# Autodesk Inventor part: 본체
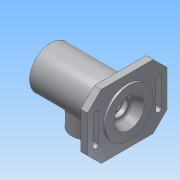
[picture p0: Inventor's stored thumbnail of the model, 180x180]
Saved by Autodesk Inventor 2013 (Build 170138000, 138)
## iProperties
Created: 2017-10
Part Number: 본체
Material: 알루미늄 6061
Document SubType Name: Modeling
Designer: Administrator
Density: 2.71 g/cm^3
Mass: 740.991 g
Surface Area: 653.939 cm^2
Volume: 273.428 cm^3
Author: Administrator
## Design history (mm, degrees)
sketch "스케치1"
  geometry: L1 (-57.5, 0)-(57.5, 0); L2 (-57.5, 0)-(-57.5, 31); L3 (-57.5, 31)-(54.5, 31); L4 (57.5, 0)-(57.5, 22); L5 (57.5, 22)-(43.5, 16); L6 (43.5, 16)-(43.5, 12.5); L7 (43.5, 12.5)-(36.2, 12.5); L8 (36.2, 12.5)-(36.2, 10); L9 (36.2, 10)-(33.5, 10); L10 (33.5, 10)-(33.5, 16.5); L11 (-48.5, 21)-(-48.5, 0); L12 (-48.5, 21)-(-48.5, 24); L13 (-48.5, 24)-(-45.5, 24); L14 (-45.5, 24)-(-45.5, 20); L15 (-45.5, 20)-(-36.5, 20); L16 (-36.5, 20)-(-36.5, 17.5); L17 (-36.5, 17.5)-(-33.25, 17.5); L18 (-33.25, 17.5)-(-33.25, 18.5); L19 (-33.25, 18.5)-(-31.5, 18.5); L20 (-31.5, 18.5)-(-31.5, 17.5); L21 (-31.5, 17.5)-(-20.5, 17.5); L22 (33.5, 16.5)-(28.5, 16.5); L23 (28.5, 16.5)-(28.5, 17.5); L24 (28.5, 17.5)-(17.5, 17.5); L25 (17.5, 17.5)-(17.5, 26); L26 (17.5, 26)-(-20.5, 26); L27 (-20.5, 26)-(-20.5, 17.5); L28 (57.5, 35)-(54.5, 35); L29 (54.5, 35)-(54.5, 31); L30 (57.5, 22)-(57.5, 35); 2 further points
  constraints: 60 end point, 16 perpendicular, 8 parallel, 1 coincident, 1 collinear, 1 horizontal, 1 midpoint, 1 point on line
  dimensions: "d0" = 115 distance of L1.start L1.end; "d1" = 31 distance of L1.start L2.end; "d11" = 14 horizontal distance of L4.end L5.end; "d12" = 6 vertical distance of L4.end L5.end; "d13" = 22 distance of L1.end L4.end; "d14" = 3.5 distance of L5.end L6.end; "d15" = 7.3 distance of L6.end L7.end; "d16" = 2.5 distance of L7.end L8.end; "d17" = 2.7 distance of L8.end L9.end; "d18" = 6.5 distance of L9.end L10.end; "d19" = 9 distance between parallel lines of L2 L11; "d20" = 21 distance of L11.start L11.end; "d21" = 3 distance of L11.start L12.end; "d22" = 3 distance of L12.end L13.end; "d23" = 4 distance of L13.end L14.end; "d25" = 9 distance of L14.end L15.end; "d26" = 2.5 distance of L15.end L16.end; "d27" = 3.25 distance of L16.end L17.end; "d28" = 1 distance of L17.end L18.end; "d29" = 1.75 distance of L18.end L19.end; "d30" = 1 distance of L19.end L20.end; "d31" = 11 distance of L20.end L21.end; "d32" = 5 distance of L10.end L22.end; "d33" = 1 distance of L22.end L23.end; "d34" = 11 distance of L23.end L24.end; "d35" = 8.5 distance of L24.end L25.end; "d102" = 52 diameter of L26 L1; "d114" = 13 distance of L4.end L28.start; "d115" = 4 distance of L3.end L28.end; "d116" = 3 distance of L28.start L28.end; "d117" = 115 horizontal distance of L2.end L28.start
revolve "회전1" sketch "스케치1" stored, may be unused: angle "d36" = 90 deg
hole "구멍1" diameter "d39" = 40.376; stored, may be unused: countersink angle "d43" = 90 deg, drill point angle "d45" = 0 deg; dims "d37" = 10, "d38" = 10, "d40" = 9, "d41" = 4, "d42" = 2, "d44" = 9
fillet "모깎기1" dims "d46" = 3, "d47" = 0.3
chamfer "모따기1" distance "d48" = 1; stored, may be unused: second distance "d49" = 2, angle "d50" = 45 deg
chamfer "모따기2" distance "d51" = 0.7; stored, may be unused: second distance "d52" = 2, angle "d53" = 30 deg
node "작업 평면1"
sketch "스케치2"
  geometry: L1 (-58, 47)-(58, 47); L2 (58, 47)-(58, -47); L3 (58, -47)-(-58, -47); L4 (-58, -47)-(-58, 47); C1 r 31 at (0, 0) reference; C2 r 21.188 at (0, 0) reference; 3 further points
  constraints: 8 end point, 2 midpoint, 2 parallel, 1 horizontal, 1 horizontal alignment, 1 perpendicular, 1 vertical alignment
  dimensions: "d55" = 116 distance of L2.end L3.end; "d56" = 94 distance of L1.end L2.end
extrude "돌출1" join sketch "스케치2" distance "d57" = 10; taper "d58" = 0 deg
chamfer "모따기3" distance "d59" = 20; stored, may be unused: second distance "d60" = 2, angle "d61" = 30 deg
node "작업 평면2"
sketch "스케치4"
  geometry: L1 (57.5, 31)-(57.5, -31) reference; C1 r 25 at (1.5, 0); 1 further point
  constraints: 1 centre point, 1 horizontal alignment
  dimensions: "d72" = 50 diameter of C1; "d74" = 56 distance from line of C1.centre L1
extrude "돌출3" join sketch "스케치4" stored distance "d75" = 10; taper "d76" = 0 deg
hole "구멍2" diameter "d79" = 32; stored, may be unused: countersink angle "d83" = 90 deg, drill point angle "d85" = 0 deg; dims "d77" = 10, "d78" = 10, "d80" = 9, "d81" = 4, "d82" = 2, "d84" = 40
sketch "스케치5"
  geometry: C1 r 16 at (0, 0) reference; 2 further points
  constraints: 1 vertical alignment
  dimensions: "d86" = 20.5 distance of C1.centre point (0, 20.5)
hole "구멍3" sketch "스케치5" at (0, 20.5) diameter "d87" = 2.459; stored, may be unused: countersink angle "d91" = 90 deg, drill point angle "d93" = 120 deg; dims "d88" = 6, "d89" = 4, "d90" = 2, "d92" = 8
fillet "모깎기2" dims "d94" = 3
node "작업 평면3"
sketch "스케치6"
  geometry: L1 (56, 78)-(56, 16) reference; L2 (25, 0)-(-25, 0) reference; 2 further points
  constraints: 1 other
  dimensions: "d95" = 56 distance from line of L1 point (0, 10); "d96" = 10 distance from line of L2 point (0, 10)
feature "엠보싱1" sketch "스케치6" dims "d97" = 0.5, "d98" = 0
sketch "스케치7"
  geometry: L1 (-47, -38)-(-47, 38) reference; L2 (-20, -50)-(20, -50); L3 (-20, -42)-(20, -42); C1 r 35 at (0, 0) reference; A1 r 4 centre (-20, -46) between (-20, -42) and (-20, -50); A2 r 4 centre (20, -46) between (20, -50) and (20, -42)
  constraints: 4 end point, 4 point on circle, 3 tangent, 2 centre point, 1 parallel, 1 perpendicular
  dimensions: "d103" = 8 diameter of A1; "d104" = 40 distance of L2.start L2.end; "d105" = 40 distance of L3.start L3.end; "d106" = 20 horizontal distance of C1.centre A1.centre; "d107" = 46 vertical distance of C1.centre A1.centre
extrude "돌출4" cut sketch "스케치7" distance "d108" = 10; taper "d109" = 0 deg
sketch "스케치9"
  geometry: L1 (-10, 54)-(0, 54) reference; L2 (-10, 0)-(-10, 54) reference; L3 (0, 0)-(-10, 0) reference; L4 (0, 0)-(0, 54) reference; 1 further point
node "솔리드1"
mirror "대칭2"
mirror "대칭3"
node "투영된 루프1"
other parameters: "d54" = 54.5, "d71" = -47
